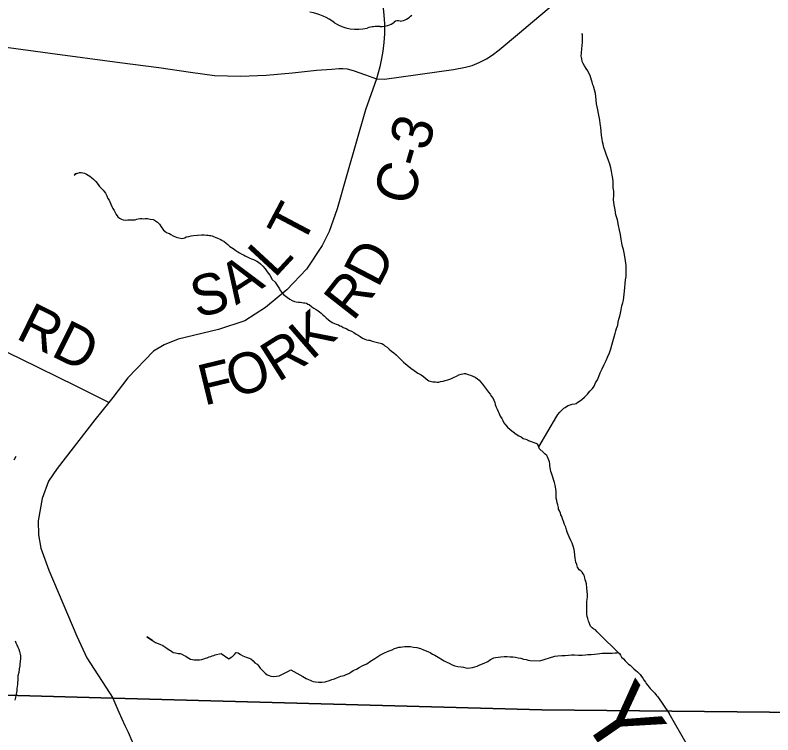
# Model space of a CAD drawing. Extents: x -14196 to 143, y -6096 to 28.
# Drawn here: x 62.952 to 64.011, y 18.706 to 19.711 of the extents above; entities that cross this region are included whole.
import ezdxf

# ---------------------------------------------------------------- set-up
doc = ezdxf.new("R2010")
doc.units = 0
for name, color, linetype in [('GM_X_Corporation', 7, 'Continuous'), ('GM_X_County_Road', 7, 'Continuous'), ('GM_X_County_Road_Text', 7, 'Continuous'), ('GM_X_Minor_River', 7, 'Continuous'), ('GM_X_Minor_River_Text', 7, 'Continuous'), ('GM_X_State_Route', 7, 'Continuous'), ('GM_X_State_Shield', 7, 'Continuous'), ('GM_X_Township_Road', 7, 'Continuous'), ('GM_X_Township_Road_Text', 7, 'Continuous')]:
    doc.layers.add(name, color=color, linetype=linetype)

msp = doc.modelspace()

# ---------------------------------------------------------------- linework, layer by layer
at = {"layer": 'GM_X_Corporation'}
msp.add_lwpolyline([(64.9028, 18.7286), (64.9028, 23.6985), (62.6174, 23.6985), (62.6129, 23.4358), (62.306, 23.4402), (62.2824, 22.5866), (62.2815, 22.5484), (62.2751, 22.2884), (62.2487, 21.1358), (62.2323, 20.4208), (62.2235, 19.866), (62.1999, 18.7816), (62.384, 18.775), (62.5403, 18.7731), (63.0887, 18.7577), (63.6879, 18.7414), (64.3696, 18.7343), (64.4266, 18.7347)], close=True, dxfattribs=at)
for points in [[(62.5403, 18.7731), (63.0887, 18.7577), (63.6879, 18.7414), (64.3696, 18.7343), (64.4266, 18.7347), (64.9028, 18.7286), (64.9028, 23.6985)], [(58.1028, 16.8985), (64.9028, 16.8985), (64.9028, 18.7286), (64.4266, 18.7347), (64.3696, 18.7343), (63.6879, 18.7414), (63.0887, 18.7577), (62.5403, 18.7731)], [(62.3117, 16.8985), (64.9028, 16.8985), (64.9028, 18.7286), (64.4266, 18.7347), (64.3696, 18.7343), (63.6879, 18.7414), (63.0887, 18.7577), (62.5403, 18.7731)]]:
    msp.add_lwpolyline(points, dxfattribs=at)
at = {"layer": 'GM_X_County_Road'}
for points in [[(62.5653, 19.7296), (62.6883, 19.7028), (62.7241, 19.6965), (62.7585, 19.6916), (62.8157, 19.6836), (63.0009, 19.6585), (63.0985, 19.6456), (63.1527, 19.6386), (63.1971, 19.6317), (63.2308, 19.6274), (63.2668, 19.6261), (63.3026, 19.6277), (63.3395, 19.6309), (63.3732, 19.6345), (63.3945, 19.6363), (63.4042, 19.637), (63.4098, 19.6371), (63.4159, 19.6365), (63.4242, 19.6342), (63.4417, 19.628), (63.4571, 19.6224)], [(63.4571, 19.6224), (63.4414, 19.5794), (63.4156, 19.4883), (63.4019, 19.4412), (63.3906, 19.4094), (63.3812, 19.3897), (63.3589, 19.3569), (63.3315, 19.328), (63.3017, 19.3033), (63.273, 19.2847), (63.236, 19.2724), (63.1798, 19.2588), (63.1602, 19.251), (63.1453, 19.2423), (63.1097, 19.2049), (63.0884, 19.1774), (63.0831, 19.1707), (63.0634, 19.1463), (63.0109, 19.0785), (62.9986, 19.0607), (62.9896, 19.0366), (62.984, 19.0053), (62.9846, 18.9858), (62.9879, 18.9673), (62.9991, 18.9366), (63.0382, 18.8444), (63.0522, 18.8142), (63.0889, 18.7572)], [(63.1169, 18.6949), (63.1157, 18.6976), (63.1104, 18.7095), (63.106, 18.7191), (63.0975, 18.7377), (63.0889, 18.7572)]]:
    msp.add_lwpolyline(points, dxfattribs=at)
at = {"layer": 'GM_X_Minor_River'}
for points in [[(63.7645, 19.5875), (63.764, 19.5928), (63.7635, 19.5981), (63.7627, 19.6023), (63.7602, 19.6122), (63.7594, 19.6144), (63.7582, 19.6178), (63.7574, 19.6209), (63.7566, 19.6239), (63.7554, 19.6273), (63.7538, 19.6307), (63.7522, 19.6337), (63.7499, 19.6371), (63.7476, 19.6409), (63.7456, 19.6439), (63.7444, 19.6469), (63.7436, 19.6503), (63.7431, 19.6541), (63.7434, 19.6591), (63.7437, 19.6644), (63.7444, 19.669), (63.7447, 19.674), (63.7446, 19.6785), (63.7445, 19.6823), (63.7445, 19.6843), (63.7437, 19.6858)], [(63.6836, 19.1088), (63.7087, 19.1513), (63.7102, 19.1539), (63.7132, 19.157), (63.7162, 19.1601), (63.7188, 19.1625), (63.7207, 19.1636), (63.7225, 19.1652), (63.7248, 19.1664), (63.7274, 19.1672), (63.7305, 19.168), (63.7339, 19.1688), (63.7358, 19.1692), (63.7384, 19.1708), (63.7407, 19.1724), (63.7437, 19.1747), (63.7474, 19.1782), (63.7515, 19.1824), (63.7552, 19.1863), (63.7586, 19.1902), (63.7612, 19.1936), (63.763, 19.1982), (63.7656, 19.2021), (63.7674, 19.2067), (63.7696, 19.2121), (63.7722, 19.2178), (63.7751, 19.2236), (63.7777, 19.2293), (63.7802, 19.2347), (63.7824, 19.2401), (63.7842, 19.2454), (63.7856, 19.2504), (63.7871, 19.2558), (63.7889, 19.2623), (63.7903, 19.2669), (63.7914, 19.2707), (63.7921, 19.2738), (63.7932, 19.2761), (63.7939, 19.2787), (63.7946, 19.2829), (63.7956, 19.2871), (63.7967, 19.2913), (63.7978, 19.2952), (63.7988, 19.2998), (63.7999, 19.3055), (63.8013, 19.3097), (63.802, 19.3135), (63.8027, 19.3177), (63.803, 19.3219), (63.8033, 19.3261), (63.8049, 19.3418), (63.8056, 19.3463), (63.8059, 19.3509), (63.8058, 19.3547), (63.8057, 19.362), (63.8048, 19.3684), (63.804, 19.3745), (63.8031, 19.3798), (63.8019, 19.3844), (63.8007, 19.3885), (63.7998, 19.3931), (63.7986, 19.3988), (63.7977, 19.4052), (63.7965, 19.4113), (63.7948, 19.4178), (63.7936, 19.4257), (63.7915, 19.4325), (63.7903, 19.4398), (63.789, 19.4466), (63.7881, 19.4534), (63.7884, 19.4599), (63.7883, 19.4656), (63.7878, 19.4702), (63.7878, 19.4748), (63.7877, 19.4793), (63.7872, 19.4835), (63.7864, 19.4881), (63.7851, 19.4938), (63.7843, 19.4983), (63.7827, 19.5036), (63.7807, 19.5097), (63.7783, 19.5161), (63.7763, 19.5214), (63.7747, 19.5267), (63.7734, 19.5313), (63.7726, 19.5347), (63.7722, 19.5385), (63.7713, 19.5434), (63.7708, 19.5495), (63.7704, 19.5544), (63.7695, 19.5601), (63.7691, 19.5647), (63.7678, 19.5693), (63.767, 19.5742), (63.7661, 19.5791), (63.7653, 19.5833), (63.7645, 19.5875)], [(63.0345, 19.4882), (63.0375, 19.4905), (63.0353, 19.4893), (63.0375, 19.4905), (63.0398, 19.4909), (63.0421, 19.4917), (63.0444, 19.4917), (63.0466, 19.4913), (63.0489, 19.491), (63.0516, 19.4895), (63.0539, 19.488), (63.0566, 19.4865), (63.0589, 19.4846), (63.0619, 19.482), (63.0646, 19.479), (63.0681, 19.4752), (63.07, 19.4722), (63.0727, 19.4696), (63.075, 19.4673), (63.0766, 19.465), (63.0781, 19.4628), (63.0801, 19.459), (63.0816, 19.4556), (63.0832, 19.4529), (63.0871, 19.4443), (63.0886, 19.4416), (63.0902, 19.4386), (63.0917, 19.4359), (63.0933, 19.4329), (63.0956, 19.4299), (63.0979, 19.428), (63.1006, 19.4265), (63.1029, 19.4258), (63.1059, 19.4254), (63.1093, 19.4255), (63.112, 19.4255), (63.1166, 19.4256), (63.1196, 19.4256), (63.1222, 19.4268), (63.1241, 19.4272), (63.1268, 19.4276), (63.1291, 19.4276), (63.1314, 19.4272), (63.1336, 19.4273), (63.137, 19.4273), (63.1409, 19.4266), (63.1447, 19.4259), (63.1466, 19.4251), (63.1508, 19.4225), (63.1539, 19.4195), (63.1562, 19.4157), (63.1593, 19.4112), (63.1612, 19.4097), (63.1635, 19.4082), (63.1658, 19.4071), (63.1677, 19.4067), (63.1696, 19.4052), (63.173, 19.4034), (63.1769, 19.4015), (63.1807, 19.4004), (63.183, 19.4), (63.1849, 19.3997), (63.1871, 19.4001), (63.189, 19.4005), (63.1909, 19.4017), (63.1947, 19.4025), (63.1981, 19.4033), (63.2011, 19.4037), (63.2125, 19.4049), (63.2163, 19.4046), (63.2194, 19.4042), (63.2216, 19.4043), (63.2235, 19.4039), (63.2254, 19.4039), (63.2274, 19.4032), (63.2293, 19.4024), (63.2316, 19.4013), (63.2346, 19.4002), (63.2373, 19.3991), (63.2392, 19.398), (63.2411, 19.3969), (63.2434, 19.3958), (63.2468, 19.3931), (63.2491, 19.3913), (63.2522, 19.3882), (63.2568, 19.3856), (63.2603, 19.383), (63.2633, 19.3811), (63.2656, 19.3796), (63.2687, 19.3778), (63.271, 19.3767), (63.2733, 19.3752), (63.2763, 19.3741), (63.2798, 19.3722), (63.2824, 19.3711), (63.2851, 19.3704), (63.287, 19.3692), (63.2897, 19.3681), (63.292, 19.3666), (63.295, 19.3644), (63.2981, 19.361)], [(63.2981, 19.361), (63.3012, 19.3572), (63.3043, 19.3531), (63.3078, 19.3486), (63.3113, 19.3425), (63.3155, 19.3384), (63.3178, 19.335), (63.3197, 19.332), (63.3213, 19.3293), (63.3225, 19.3271), (63.3248, 19.324), (63.3275, 19.321), (63.3359, 19.315), (63.339, 19.3132), (63.3424, 19.3117), (63.3447, 19.3113), (63.3481, 19.3106), (63.3504, 19.3106), (63.3527, 19.3103), (63.355, 19.3099), (63.3569, 19.3096), (63.3591, 19.3092), (63.3611, 19.3081), (63.363, 19.3073), (63.3668, 19.3043), (63.3695, 19.3025), (63.3725, 19.3006), (63.3752, 19.2987), (63.3775, 19.2972), (63.3794, 19.2954), (63.3821, 19.2931), (63.3844, 19.2912), (63.3867, 19.289), (63.3898, 19.286), (63.3917, 19.2845), (63.3948, 19.2822), (63.3982, 19.2811), (63.4005, 19.28), (63.4036, 19.2789), (63.4059, 19.2778), (63.4081, 19.277), (63.4104, 19.2752), (63.4146, 19.2737), (63.4181, 19.2718), (63.4219, 19.27), (63.4253, 19.2681), (63.4284, 19.2662), (63.4315, 19.2644), (63.4341, 19.2625), (63.4372, 19.2603), (63.4406, 19.2588), (63.4429, 19.258), (63.4456, 19.2577), (63.4475, 19.2577), (63.4509, 19.2562), (63.4601, 19.254), (63.4627, 19.2533), (63.4646, 19.2529), (63.4669, 19.2514), (63.4685, 19.2496), (63.4719, 19.2477), (63.4746, 19.2451), (63.4777, 19.2424), (63.4811, 19.2398), (63.4842, 19.2372), (63.4869, 19.2346), (63.4904, 19.2312), (63.4946, 19.227), (63.4996, 19.2225), (63.5049, 19.2184), (63.5095, 19.2154), (63.5149, 19.2117), (63.5191, 19.2094), (63.5226, 19.2068), (63.5264, 19.2034), (63.5302, 19.2008), (63.5337, 19.1997), (63.5356, 19.1994), (63.5394, 19.1994), (63.5416, 19.199), (63.5439, 19.1991), (63.5462, 19.1998), (63.55, 19.2003), (63.553, 19.2011), (63.5568, 19.2022), (63.5606, 19.2038), (63.5644, 19.2054), (63.5685, 19.2073), (63.5719, 19.2092), (63.5753, 19.21), (63.5776, 19.2108), (63.5795, 19.2112), (63.5814, 19.2112), (63.5852, 19.2098), (63.5882, 19.2087), (63.5917, 19.2072), (63.5947, 19.2061), (63.5982, 19.2034), (63.6005, 19.2016), (63.6028, 19.1989), (63.6051, 19.1963)], [(63.6051, 19.1963), (63.6132, 19.185), (63.6155, 19.182), (63.6178, 19.179), (63.6198, 19.1763), (63.6209, 19.1737), (63.6221, 19.1706), (63.6229, 19.1676), (63.6241, 19.1642), (63.6257, 19.1612), (63.6268, 19.1581), (63.628, 19.1559), (63.6299, 19.1517), (63.6319, 19.1483), (63.6334, 19.1453), (63.635, 19.1423), (63.6373, 19.1393), (63.64, 19.1362), (63.6435, 19.1329), (63.6477, 19.1295), (63.6519, 19.1265), (63.6557, 19.1239), (63.6592, 19.1224), (63.6618, 19.1205), (63.6657, 19.1194), (63.6679, 19.1183), (63.6695, 19.1176), (63.6819, 19.1127)], [(63.7944, 18.8214), (63.7693, 18.8461), (63.7677, 18.848), (63.7654, 18.8502), (63.7627, 18.8532), (63.7607, 18.854), (63.7581, 18.8558), (63.7561, 18.8584), (63.7549, 18.8607), (63.7541, 18.8634), (63.7529, 18.8652), (63.7521, 18.8687), (63.7513, 18.8717), (63.7509, 18.8751), (63.7508, 18.8793), (63.7507, 18.8835), (63.7506, 18.8884), (63.7509, 18.8923), (63.7513, 18.8957), (63.7516, 18.8987), (63.7515, 18.9025), (63.7511, 18.9067), (63.751, 18.9117), (63.7501, 18.9174), (63.7493, 18.9204), (63.7485, 18.9231), (63.7481, 18.9257), (63.7477, 18.9276), (63.7469, 18.9295), (63.7457, 18.9314), (63.7441, 18.9336), (63.7422, 18.9355), (63.7403, 18.937), (63.7379, 18.9408), (63.7367, 18.9442), (63.7355, 18.9476), (63.7351, 18.9502), (63.7347, 18.9533), (63.7334, 18.962), (63.7329, 18.9654), (63.7317, 18.97), (63.7301, 18.9742), (63.7285, 18.9779), (63.7262, 18.9828), (63.7246, 18.9862), (63.7234, 18.9897), (63.7226, 18.9927), (63.7214, 18.9965), (63.7198, 19.0003), (63.7182, 19.0044), (63.717, 19.0082), (63.7158, 19.0112), (63.7146, 19.0135), (63.7138, 19.0162), (63.7126, 19.0192), (63.7114, 19.0218), (63.711, 19.0241), (63.7102, 19.0275), (63.7093, 19.0305), (63.7089, 19.0336), (63.7081, 19.037), (63.708, 19.0419), (63.7079, 19.0458), (63.7075, 19.0499), (63.7066, 19.0549), (63.7054, 19.0587), (63.7042, 19.0628), (63.7034, 19.0662), (63.7022, 19.0689), (63.7014, 19.0719), (63.7006, 19.0742), (63.6998, 19.0772), (63.6994, 19.0795), (63.6989, 19.0825), (63.6989, 19.0848), (63.6985, 19.0875), (63.6977, 19.0898), (63.6968, 19.0924), (63.696, 19.0947), (63.6949, 19.0966), (63.6926, 19.0984), (63.6902, 19.1007), (63.6848, 19.1059), (63.6819, 19.1127)], [(62.953, 19.0951), (62.9504, 19.0898)], [(63.136, 18.8432), (63.1441, 18.8384), (63.136, 18.8432), (63.1441, 18.8384), (63.1483, 18.8354), (63.1544, 18.8332), (63.1582, 18.8313), (63.1613, 18.8294), (63.164, 18.8276), (63.1659, 18.8261), (63.1682, 18.8246), (63.1705, 18.8231), (63.1728, 18.8216), (63.1762, 18.8208), (63.18, 18.8201), (63.1827, 18.8198), (63.185, 18.819), (63.1884, 18.8172), (63.1903, 18.8161), (63.1922, 18.8149), (63.1945, 18.8134), (63.1972, 18.8123), (63.1999, 18.8116), (63.2021, 18.8112), (63.2056, 18.8113), (63.2094, 18.8113), (63.2128, 18.8117), (63.2158, 18.8125), (63.2181, 18.8133), (63.2203, 18.8141), (63.223, 18.8153), (63.2253, 18.816), (63.2275, 18.8168), (63.2298, 18.8172), (63.2317, 18.818), (63.2336, 18.8184), (63.2377, 18.8196), (63.24, 18.82), (63.2504, 18.8125), (63.2538, 18.8148), (63.2556, 18.816), (63.2583, 18.8187), (63.2609, 18.8214), (63.2636, 18.821), (63.267, 18.8188), (63.2701, 18.8169), (63.2746, 18.8151), (63.2788, 18.8136), (63.2815, 18.8125), (63.2846, 18.8098), (63.2869, 18.8072), (63.29, 18.805), (63.2923, 18.8023), (63.2946, 18.7997), (63.2965, 18.7974), (63.2988, 18.7952), (63.3015, 18.7925), (63.3042, 18.7903), (63.3069, 18.7892), (63.3091, 18.7884), (63.3126, 18.7881), (63.3171, 18.7885), (63.3209, 18.7889), (63.3247, 18.7905), (63.3292, 18.7932), (63.3341, 18.7955), (63.3371, 18.7971), (63.354, 18.7878), (63.3586, 18.7852), (63.362, 18.7837), (63.3643, 18.7826), (63.3662, 18.7818), (63.3685, 18.7811), (63.3719, 18.7804), (63.3761, 18.78), (63.3807, 18.7801), (63.3852, 18.7805), (63.3882, 18.7813), (63.3913, 18.7825), (63.3947, 18.7837), (63.3984, 18.7848), (63.4026, 18.7864), (63.4071, 18.7883), (63.4117, 18.7895), (63.4147, 18.7907), (63.4181, 18.7919), (63.4211, 18.7938), (63.4245, 18.7961), (63.4291, 18.7981), (63.4328, 18.8004), (63.4377, 18.8031), (63.4434, 18.8058), (63.4487, 18.8093), (63.4547, 18.8132), (63.4615, 18.8178), (63.4679, 18.8209), (63.4721, 18.8229), (63.4758, 18.824), (63.4789, 18.8252), (63.4823, 18.8268), (63.4853, 18.8279)], [(62.9519, 18.8378), (62.9531, 18.8348), (62.9546, 18.8322), (62.9558, 18.8291), (62.957, 18.8261), (62.9581, 18.8227), (62.959, 18.8193), (62.9594, 18.8166), (62.9594, 18.8132), (62.9591, 18.8087), (62.9587, 18.8056), (62.9584, 18.8026), (62.9577, 18.7984), (62.957, 18.7934), (62.9559, 18.7889), (62.9556, 18.7858), (62.9556, 18.7828), (62.9552, 18.7797), (62.9553, 18.7767), (62.9549, 18.774), (62.9546, 18.771), (62.9542, 18.768), (62.9539, 18.7657), (62.9535, 18.7638), (62.9532, 18.7615), (62.9525, 18.7588), (62.9517, 18.7549)], [(63.4853, 18.8279), (63.4879, 18.8287), (63.4906, 18.8291), (63.4933, 18.8295), (63.4967, 18.83), (63.5005, 18.8296), (63.5046, 18.8297), (63.5088, 18.8289), (63.5134, 18.8282), (63.5184, 18.8268), (63.5226, 18.8253), (63.5264, 18.8238), (63.5294, 18.8223), (63.5321, 18.8212), (63.5352, 18.8193), (63.5382, 18.8179), (63.5409, 18.8164), (63.5516, 18.81), (63.5554, 18.8078), (63.5585, 18.8063), (63.5627, 18.8044), (63.5665, 18.803), (63.5707, 18.8019), (63.5753, 18.8012), (63.5787, 18.8008), (63.5817, 18.8001), (63.5844, 18.7997), (63.5878, 18.7998), (63.5912, 18.8006), (63.5942, 18.8014), (63.5977, 18.8025), (63.6011, 18.8041), (63.6052, 18.8057), (63.6082, 18.8068), (63.6105, 18.808), (63.6124, 18.8088), (63.615, 18.8107), (63.6173, 18.8122), (63.6207, 18.8138), (63.6233, 18.8146), (63.6271, 18.815), (63.6305, 18.8154), (63.6351, 18.8159), (63.6397, 18.8159), (63.6438, 18.8156), (63.6476, 18.8152), (63.6511, 18.8149), (63.6549, 18.8142), (63.6587, 18.8134), (63.6625, 18.8123), (63.6659, 18.8116), (63.6686, 18.8105), (63.6716, 18.8102), (63.6852, 18.8098)], [(63.6852, 18.8098), (63.7059, 18.8165), (63.7105, 18.8169), (63.7158, 18.817), (63.7207, 18.8171), (63.7253, 18.8176), (63.7295, 18.818), (63.7336, 18.8181), (63.7393, 18.8178), (63.7443, 18.8179), (63.7488, 18.8183), (63.7523, 18.8184), (63.7568, 18.8185), (63.7614, 18.8189), (63.7655, 18.8194), (63.769, 18.8198), (63.7724, 18.8203), (63.7758, 18.8203), (63.78, 18.8204), (63.7838, 18.8204), (63.786, 18.8205), (63.7902, 18.8209), (63.7925, 18.821), (63.7944, 18.8214), (63.7963, 18.8199), (63.7979, 18.8176), (63.7994, 18.815), (63.8018, 18.8124), (63.8045, 18.8098), (63.8068, 18.8075), (63.8091, 18.8053), (63.8111, 18.8038), (63.813, 18.8019), (63.8165, 18.7985), (63.8192, 18.7963), (63.8215, 18.7944), (63.8234, 18.7926), (63.8253, 18.7907), (63.8273, 18.7881), (63.8289, 18.7854), (63.8308, 18.7824), (63.8328, 18.7798), (63.8339, 18.7779), (63.8355, 18.776), (63.8378, 18.773), (63.8394, 18.7711), (63.8413, 18.7692), (63.8429, 18.7674), (63.8456, 18.7644), (63.8483, 18.7614), (63.8498, 18.7595), (63.866, 18.736)], [(62.9524, 18.7584), (62.9525, 18.7584)], [(63.8915, 18.6917), (63.866, 18.736)]]:
    msp.add_lwpolyline(points, dxfattribs=at)
at = {"layer": 'GM_X_State_Route'}
for points in [[(63.4571, 19.6224), (63.468, 19.6219), (63.5644, 19.6358), (63.5811, 19.639), (63.5904, 19.6413), (63.6005, 19.6453), (63.6105, 19.6503), (63.6187, 19.6556), (63.6285, 19.6629), (63.6569, 19.6866), (63.6747, 19.7023), (63.7243, 19.7439)], [(63.4658, 19.7257), (63.4673, 19.7114), (63.4679, 19.6994), (63.4679, 19.6854), (63.4673, 19.6733), (63.4659, 19.6612), (63.4641, 19.6511), (63.4614, 19.6393), (63.4571, 19.6224)]]:
    msp.add_lwpolyline(points, dxfattribs=at)
at = {"layer": 'GM_X_State_Shield'}
for centre, major_axis, start_param, end_param in [((63.3446, 19.6545), (0.079, 0), 0.823519, 1.323587), ((63.4836, 19.725), (0.0282, 0), 4.937069, 5.64225), ((63.43, 19.7319), (0.0501, 0), 4.026481, 4.996735), ((63.4626, 19.7169), (0.0267, 0), 4.691044, 5.507374), ((63.4868, 19.6975), (0.00752, 0), 1.147584, 2.315152), ((63.459, 19.6627), (0.0412, 0), 1.495662, 1.94098)]:
    msp.add_ellipse(centre, major_axis=major_axis, ratio=0.8, start_param=start_param, end_param=end_param, dxfattribs=at)
at = {"layer": 'GM_X_Township_Road'}
msp.add_lwpolyline([(63.0831, 19.1707), (63.0375, 19.1935), (62.9594, 19.2315), (62.9137, 19.2535)], dxfattribs=at)

# ---------------------------------------------------------------- texts
at = {"layer": 'GM_X_County_Road_Text'}
for s, height, rotation, p in [('C-3', 0.05682, 73.7322, (63.5058, 19.4434)), ('T', 0.0568, 62.0894, (63.3526, 19.3874)), ('D', 0.0568, 62.5112, (63.4592, 19.3291)), ('L', 0.0568, 47.262, (63.3145, 19.3431)), ('A', 0.0568, 32.8579, (63.2606, 19.3059)), ('S', 0.0568, 15.1276, (63.2061, 19.2882)), ('R', 0.0568, 51.9235, (63.4242, 19.2827)), ('K', 0.0568, 40.9169, (63.3663, 19.2286)), ('R', 0.0568, 32.2913, (63.3193, 19.1981)), ('O', 0.0568, 17.66, (63.2574, 19.1762)), ('F', 0.0568, 13.5972, (63.2159, 19.166))]:
    msp.add_text(s, height=height, rotation=rotation, dxfattribs=at).set_placement(p)
at = {"layer": 'GM_X_Minor_River_Text'}
msp.add_text('Yellow', height=0.09467, rotation=304.6008, dxfattribs=at).set_placement((63.7388, 18.7352))
at = {"layer": 'GM_X_Township_Road_Text'}
msp.add_text('RD', height=0.05682, rotation=333.6566, dxfattribs=at).set_placement((62.9513, 19.2609))

doc.saveas('drawing.dxf')
